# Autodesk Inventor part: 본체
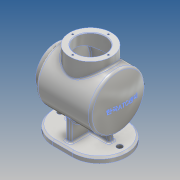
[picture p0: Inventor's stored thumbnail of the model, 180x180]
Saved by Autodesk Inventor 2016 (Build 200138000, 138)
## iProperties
Created: 2016-04
Part Number: 본체
Material: 알루미늄 6061
Document SubType Name: Modeling
Designer: Administrator
Density: 2.7 g/cm^3
Appearance: 알루미늄 - 평지
Mass: 1016.92 g
Surface Area: 1209.17 cm^2
Volume: 376.636 cm^3
Author: Administrator
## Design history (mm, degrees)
sketch "스케치1"
  geometry: L1 (-17.5, -50)-(17.5, -50); L2 (67.5, 0)-(67.5, 0); L3 (17.5, 50)-(-17.5, 50); L4 (-67.5, 0)-(-67.5, 0); L5 (-67.5, -50)-(67.5, 50); L6 (67.5, -50)-(-67.5, 50); A1 r 50 centre (-17.5, 0) between (-17.5, 50) and (-67.5, 0); A2 r 50 centre (-17.5, 0) between (-67.5, 0) and (-17.5, -50); A3 r 50 centre (17.5, 0) between (17.5, -50) and (67.5, 0); A4 r 50 centre (17.5, 0) between (67.5, 0) and (17.5, 50); 1 further point
  constraints: 12 end point, 8 point on circle, 8 point on line, 8 tangent, 4 centre point, 3 equal radius, 2 midpoint, 2 parallel, 1 horizontal, 1 perpendicular
  dimensions: "d0" = 135 distance of L6.end L5.end; "d1" = 100 distance of L5.end L6.start; "d2" = 50 radius of A1
extrude "돌출1" new body sketch "스케치1" distance "d3" = 10; taper "d4" = 0 deg
sketch "스케치2"
  geometry: 3 further points
  constraints: 2 horizontal alignment
  dimensions: "d8" = 54 distance of point (0, 0) point (54, 0); "d9" = 54 distance of point (0, 0) point (-54, 0)
hole "구멍1" sketch "스케치2" at (54, 0), (-54, 0) diameter "d10" = 10; stored, may be unused: countersink angle "d14" = 90 deg, drill point angle "d16" = 118 deg; dims "d11" = 6, "d12" = 4, "d13" = 2, "d15" = 8
sketch "스케치4"
  geometry: L1 (61, 79)-(-61, 79); L2 (49, 129)-(-50.087, 129); L3 (49, 129)-(49, 117); L4 (49, 117)-(61, 117); L5 (61, 117)-(61, 79); L6 (-17.5, 0)-(17.5, 0) reference; A1 r 120 centre (59, 79) between (-50.087, 129) and (-61, 79); 3 further points
  constraints: 10 end point, 3 horizontal, 2 midpoint, 2 perpendicular, 2 point on circle, 1 centre point, 1 point on line, 1 vertical alignment
  dimensions: "d19" = 79 distance from line of point (0, 0) L1; "d33" = 110 distance from line of L1.end L3; "d34" = 120 radius of A1; "d35" = 100 diameter of L2 L1; "d37" = 12 distance of L3.end L4.end; "d38" = 76 diameter of L4 L1
revolve "회전1" sketch "스케치4" stored, may be unused: angle "d39" = 90 deg
node "작업 평면1"
sketch "스케치6"
  geometry: L1 (-49, 50)-(-49, -50) reference; C1 r 38 at (1, 0); 2 further points
  constraints: 1 centre point, 1 coincident, 1 horizontal alignment, 1 midpoint
  dimensions: "d41" = 76 diameter of C1; "d114" = 50 distance from line of L1 point (1, 0)
extrude "돌출2" join sketch "스케치6" distance "d42" = 65; taper "d43" = 0 deg
sketch "스케치7"
  geometry: L1 (61, 41)-(61, 117) reference; L2 (61, 79)-(-90.061, 79); L3 (61, 106)-(46, 106); L4 (46, 106)-(46, 126); L5 (46, 126)-(-48.145, 126); L6 (37, 144)-(-39, 144) reference; L7 (-50.087, 129)-(49, 129) reference; L8 (49, 117)-(61, 117) reference; L9 (49, 29)-(49, 129) reference; L10 (37, 129)-(37, 144) reference; L11 (-39, 129)-(-39, 144) reference; A1 r 120 centre (59, 79) between (-50.087, 129) and (-50.087, 29) reference; A2 r 117 centre (59, 79) between (-48.145, 126) and (-58, 79); 3 further points
  constraints: 8 end point, 3 point on line, 2 horizontal, 2 midpoint, 2 perpendicular, 2 point on circle, 1 centre point, 1 coincident
  dimensions: "d46" = 54 diameter of L3 L2; "d47" = 3 distance between parallel lines of L9 L4; "d48" = 3 distance between parallel lines of L7 L5; "d113" = 117 radius of A2
revolve "회전2" sketch "스케치7" stored, may be unused: angle "d50" = 90 deg
sketch "스케치8"
  geometry: 1 further point
sketch "스케치9"
  geometry: C1 r 38 at (0, 0) reference; C2 r 27 at (0, 0)
  constraints: 1 centre point, 1 coincident
  dimensions: "d51" = 54 diameter of C2
extrude "돌출3" cut sketch "스케치9" distance "d52" = 65; taper "d53" = 0 deg
sketch "스케치11"
  geometry: L1 (-50.087, 29)-(49, 29) reference; L2 (34.71, 40)-(40, 10); L3 (67.5, 10)-(17.5, 10) reference; L4 (-34.71, 40)-(-40, 10); L5 (-17.5, 10)-(-67.5, 10) reference; L6 (40, 10)-(-40, 10); L7 (34.71, 40)-(-34.71, 40); 1 further point
  constraints: 8 end point, 2 point on line, 1 collinear, 1 horizontal
  dimensions: "d54" = 100 deg angle of L5 L4; "d55" = 100 deg angle of L3 L2; "d56" = 40 horizontal distance of point (0, 0) L2.end; "d57" = 40 horizontal distance of point (0, 0) L4.end; "d58" = 40 distance from line of point (0, 0) L7
extrude "돌출4" join sketch "스케치11" stored distance "d59" = 10; taper "d60" = 0 deg
sketch "스케치12"
  geometry: C1 r 47 at (0, 79) reference; C2 r 47 at (0, 79); 1 further point
  constraints: 1 centre point, 1 coincident, 1 concentric
extrude "돌출5" cut sketch "스케치12" stored distance "d61" = 80; taper "d62" = 0 deg
sketch "스케치13"
  geometry: L1 (40, 5)-(40, 55); L2 (40, 55)-(-40, 55); L3 (-40, 55)-(-40, 5); L4 (50, 0)-(-50, 0) reference; L5 (50, 0)-(50, 10) reference; L6 (-50, 10)-(50, 10) reference; L7 (-50, 0)-(-50, 10) reference; L8 (40, 5)-(-40, 5); 1 further point
  constraints: 8 end point, 2 perpendicular, 1 parallel, 1 vertical
  dimensions: "d63" = 40 distance from line of point (0, 0) L1; "d64" = 40 distance from line of L3 point (0, 0); "d65" = 55 distance from line of point (0, 0) L2; "d66" = 5 distance from line of L4 L3.end
extrude "돌출6" join sketch "스케치13" stored distance "d67" = 10; taper "d68" = 0 deg
sketch "스케치14"
  geometry: C1 r 47 at (0, 79) reference; C2 r 47 at (0, 79); 1 further point
  constraints: 1 centre point, 1 coincident, 1 concentric
extrude "돌출7" cut sketch "스케치14" stored distance "d69" = 80; taper "d70" = 0 deg
sketch "스케치15"
  geometry: C1 r 27 at (0, 0) reference; 2 further points
  constraints: 1 horizontal alignment
  dimensions: "d71" = 32.5 distance of C1.centre point (32.5, 0)
hole "구멍2" sketch "스케치15" at (32.5, 0) diameter "d72" = 3.242; stored, may be unused: countersink angle "d76" = 90 deg, drill point angle "d78" = 118 deg; dims "d73" = 8, "d74" = 4, "d75" = 2, "d77" = 10
sketch "스케치16"
  geometry: C1 r 27 at (0, 0) reference; 1 further point
  constraints: 1 horizontal alignment
  dimensions: "d82" = 32.5 distance of C1.centre point (32.5, 0)
hole "구멍3" sketch "스케치16" at (32.5, 0) diameter "d83" = 3.242; stored, may be unused: countersink angle "d87" = 90 deg, drill point angle "d89" = 118 deg; dims "d84" = 8, "d85" = 4, "d86" = 2, "d88" = 10
chamfer "모따기1" distance "d93" = 1; stored, may be unused: second distance "d94" = 2, angle "d95" = 45 deg
fillet "모깎기1" dims "d96" = 2
chamfer "모따기2" distance "d97" = 3; stored, may be unused: second distance "d98" = 2, angle "d99" = 45 deg
fillet "모깎기2" dims "d100" = 5
fillet "모깎기3" dims "d101" = 3
node "작업 평면5"
sketch "스케치21"
  geometry: L1 (79, -50)-(79, 50) reference; 3 further points
  constraints: 1 horizontal alignment, 1 midpoint, 1 other
  dimensions: "d106" = 79 distance from line of L1 point (0, 0)
feature "엠보싱1" sketch "스케치21" dims "d0" = 135, "d1" = 100, "d2" = 50, "d107" = 0.5, "d108" = 0
node "솔리드1"
pattern_circular "원형 패턴1" dims angle "d80" = 360 deg
pattern_circular "원형 패턴2" dims angle "d91" = 360 deg
node "투영된 루프2"
node "투영된 루프3"
other parameters: "d40" = 79, "d105" = 109
